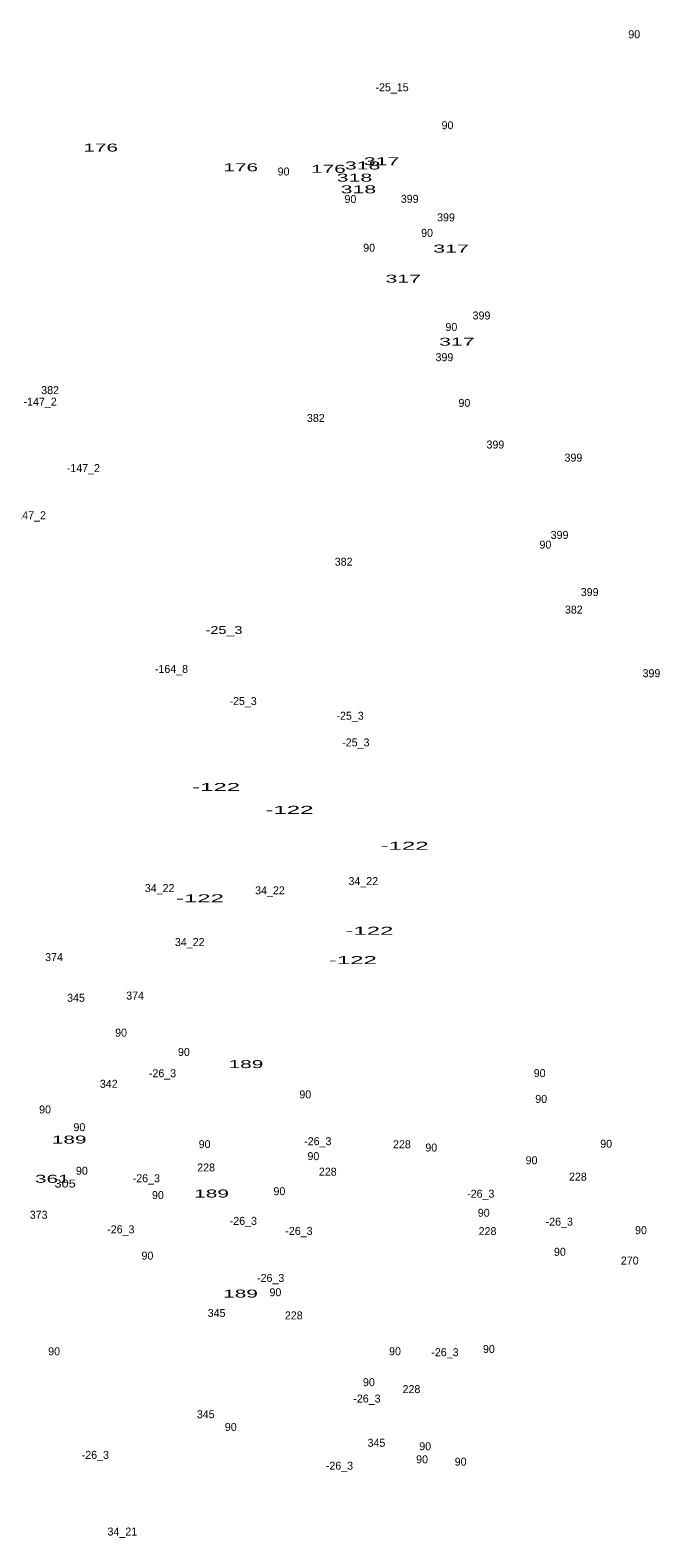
# Model space of a CAD drawing. Extents: x -662499 to -659675, y -1001682 to -998165.
# Drawn here: x -660787 to -660471, y -999943 to -999186 of the extents above; entities that cross this region are included whole.
import ezdxf
from ezdxf.enums import TextEntityAlignment as Align

# ---------------------------------------------------------------- set-up
doc = ezdxf.new("R2010")
doc.units = 0
doc.header["$LTSCALE"] = 1.6
doc.layers.add('24', color=7, linetype='Continuous')

msp = doc.modelspace()

# ---------------------------------------------------------------- texts
at = {"layer": '24'}
for s, p in [('90', (-660483.957, -999190.19)), ('-25_15', (-660605.506, -999216.81)), ('90', (-660577.677, -999235.85)), ('90', (-660659.967, -999259.09)), ('90', (-660626.417, -999272.91)), ('399', (-660596.668, -999272.8)), ('399', (-660578.438, -999282.11)), ('90', (-660587.937, -999289.88)), ('90', (-660617.027, -999297.36)), ('399', (-660560.608, -999331.37)), ('90', (-660575.737, -999337.15)), ('399', (-660579.218, -999352.32)), ('382', (-660777.167, -999368.86)), ('-147_2', (-660782.176, -999374.64)), ('90', (-660569.197, -999375.23)), ('382', (-660643.787, -999382.82)), ('399', (-660553.628, -999396.15)), ('-147_2', (-660760.466, -999407.99)), ('399', (-660514.468, -999402.74)), ('-147_2', (-660787.606, -999431.65)), ('90', (-660528.537, -999446.4)), ('399', (-660521.438, -999441.53)), ('382', (-660629.827, -999454.97)), ('399', (-660506.318, -999470.23)), ('382', (-660514.277, -999479.02)), ('-164_8', (-660716.256, -999508.82)), ('399', (-660475.298, -999510.96)), ('-25_3', (-660680.292, -999524.94)), ('-25_3', (-660626.592, -999532.31)), ('-25_3', (-660623.692, -999545.69)), ('34_22', (-660722.18, -999618.81)), ('34_22', (-660666.8, -999619.97)), ('34_22', (-660619.94, -999615.32)), ('34_22', (-660707.08, -999645.93)), ('374', (-660775.207, -999653.48)), ('345', (-660764.171, -999673.9)), ('374', (-660734.497, -999672.78)), ('90', (-660741.547, -999691.41)), ('90', (-660709.987, -999701.09)), ('-26_3', (-660720.728, -999711.79)), ('90', (-660531.417, -999711.71)), ('342', (-660747.741, -999717.09)), ('90', (-660649.067, -999722.39)), ('90', (-660530.647, -999724.67)), ('90', (-660779.697, -999729.95)), ('90', (-660762.457, -999738.86)), ('90', (-660699.607, -999747.38)), ('-26_3', (-660642.788, -999745.89)), ('228', (-660600.567, -999747.43)), ('90', (-660585.827, -999749.08)), ('90', (-660498.037, -999747.16)), ('90', (-660645.007, -999753.38)), ('90', (-660535.487, -999755.47)), ('90', (-660761.217, -999760.72)), ('-26_3', (-660728.868, -999764.5)), ('228', (-660698.857, -999759.07)), ('228', (-660637.787, -999761.2)), ('228', (-660512.217, -999763.7)), ('90', (-660723.037, -999772.95)), ('90', (-660662.047, -999771.01)), ('-26_3', (-660560.978, -999772.26)), ('373', (-660782.913, -999782.83)), ('-26_3', (-660680.168, -999785.88)), ('90', (-660559.497, -999781.82)), ('-26_3', (-660521.578, -999786.27)), ('-26_3', (-660741.658, -999790.14)), ('-26_3', (-660652.248, -999790.92)), ('228', (-660557.587, -999791.05)), ('90', (-660480.547, -999790.55)), ('90', (-660728.307, -999803.34)), ('90', (-660521.267, -999801.4)), ('270', (-660486.197, -999805.8)), ('-26_3', (-660666.438, -999814.54)), ('90', (-660664.057, -999821.72)), ('345', (-660693.601, -999832.14)), ('228', (-660654.847, -999833.35)), ('90', (-660775.167, -999851.37)), ('90', (-660604.027, -999851.36)), ('-26_3', (-660578.968, -999851.82)), ('90', (-660556.897, -999850.21)), ('90', (-660617.157, -999866.87)), ('228', (-660595.777, -999870.36)), ('-26_3', (-660618.128, -999875.09)), ('345', (-660699.031, -999882.95)), ('90', (-660686.477, -999889.34)), ('345', (-660613.341, -999897.3)), ('90', (-660588.887, -999899.03)), ('-26_3', (-660754.458, -999903.36)), ('-26_3', (-660631.928, -999908.79)), ('90', (-660590.437, -999905.61)), ('90', (-660571.077, -999906.77)), ('34_21', (-660740.903, -999941.86))]:
    msp.add_text(s, height=4, dxfattribs=at).set_placement(p, align=Align.CENTER)
for s, width, p in [('176', 1.95, (-660751.787, -999247.08)), ('176', 1.95, (-660681.467, -999256.97)), ('176', 1.95, (-660637.457, -999257.74)), ('318', 2, (-660620.307, -999256.05)), ('317', 2, (-660610.793, -999253.94)), ('318', 2, (-660624.377, -999262.16)), ('318', 2, (-660622.397, -999268.03)), ('317', 2, (-660575.893, -999297.78)), ('317', 2, (-660599.933, -999312.9)), ('317', 2, (-660572.993, -999344.52)), ('-25_3', 1.35, (-660689.86, -999489.26)), ('-122', 2.25, (-660693.821, -999568.1)), ('-122', 2.25, (-660656.991, -999579.55)), ('-122', 2.25, (-660599.211, -999597.58)), ('-122', 2.25, (-660701.961, -999623.96)), ('-122', 2.25, (-660616.861, -999640.25)), ('-122', 2.25, (-660625.191, -999654.99)), ('189', 1.95, (-660678.853, -999707.19)), ('189', 1.95, (-660767.603, -999745.08)), ('361', 1.95, (-660776.073, -999764.76)), ('305', 1.2, (-660769.63, -999767.15)), ('189', 1.95, (-660696.113, -999772.16)), ('189', 1.95, (-660681.573, -999822.39))]:
    msp.add_text(s, height=4, dxfattribs=dict(at, width=width)).set_placement(p, align=Align.CENTER)

doc.saveas('drawing.dxf')
